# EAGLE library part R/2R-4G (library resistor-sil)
R/2R Ladder 4 Murata RGSD8L
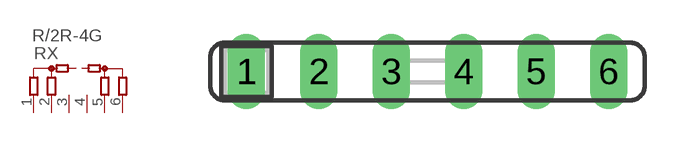
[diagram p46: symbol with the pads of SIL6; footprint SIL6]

Designator prefix RX

## R/2R-4G (OC_FARNELL: unknown; OC_NEWARK: unknown)  [SIL6]
1  IN  pas
2  B4  pas
3  B3  pas
4  B2  pas
5  B1  pas
6  OUT  pas

## Footprint SIL6 (pad centres in mm)
Single In Line
drill 0.813 long: 1 -6.35,0; 2 -3.81,0; 3 -1.27,0; 4 1.27,0; 5 3.81,0; 6 6.35,0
